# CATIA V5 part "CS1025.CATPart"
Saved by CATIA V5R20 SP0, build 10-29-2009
Part number: CS1025
Revision: 4
Definition: design
Nomenclature: CS1025
Source: made
Description: NOT SPECIFIED
Bounding box of the stored display mesh (mm): x -23.825 to 24, y -24 to 24, z -45 to 12
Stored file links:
  C:\Users\Raffaele\Desktop\3D X SITO CF\BOLEX\20-TILTED COLUMN SUPPORT\CS1025.CATPart
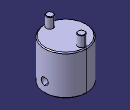
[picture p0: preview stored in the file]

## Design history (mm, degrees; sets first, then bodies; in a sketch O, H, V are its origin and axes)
Body1 "MANIFOLD_SOLID_BREP #711" (main body)
  Solid1: solid without history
